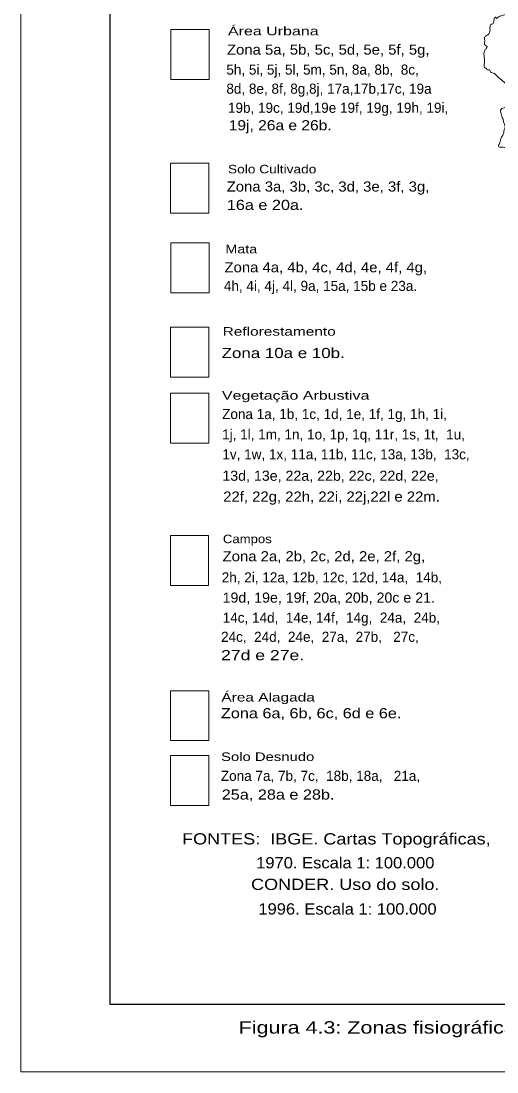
# Model space of a CAD drawing. Extents: x 854879 to 917879, y 8541948 to 8631048.
# Drawn here: x 854879 to 876061, y 8541948 to 8588670 of the extents above; entities that cross this region are included whole.
import ezdxf
from ezdxf.enums import TextEntityAlignment as Align

# ---------------------------------------------------------------- set-up
doc = ezdxf.new("R2010")
doc.units = 0
doc.header["$LTSCALE"] = 150
for name, color, linetype, lineweight in [('1', 7, 'Continuous', 13), ('18', 7, 'Continuous', 13), ('3', 7, 'Continuous', 13), ('35', 7, 'Continuous', 13), ('36', 7, 'Continuous', 13), ('44', 7, 'Continuous', 13), ('59', 7, 'Continuous', 13)]:
    doc.layers.add(name, color=color, linetype=linetype, lineweight=lineweight)
doc.layers.add('53', color=7, linetype='Continuous')
doc.layers.add('61', color=7, linetype='Continuous')

msp = doc.modelspace()

# ---------------------------------------------------------------- linework, layer by layer
at = {"layer": '1'}
msp.add_lwpolyline([(916445.6, 8586427.1), (916445.6, 8544954.2), (858846.4, 8544954.2), (858846.4, 8599885.6)], dxfattribs=at)
at = {"layer": '18'}
msp.add_spline([(877858.6, 8588369.4), (877792.5, 8588367.9), (877766.7, 8588347.9), (877740.8, 8588317.8), (877758.5, 8588312.4), (877760.4, 8588276.7), (877713.5, 8588211.2), (877611.3, 8588187.3), (877502.6, 8588217.1), (877391, 8588231.7), (877300.1, 8588268.9), (877141, 8588470.3), (877003.5, 8588600), (876874, 8588607.2), (876786, 8588659.6), (876742, 8588757.2), (876715.1, 8588818.8), (876619, 8588848.4), (876473.6, 8588960.4), (876297.4, 8588914.8), (876092.3, 8588821.3), (876038.3, 8588786.5), (875996.1, 8588843.3), (875955.1, 8588826.1), (875936.2, 8588760.1), (875927.4, 8588699.1), (875910.3, 8588594.8), (875853.5, 8588544.8), (875794.6, 8588517.7), (875760.7, 8588469.8), (875749.9, 8588296.6), (875722.2, 8588167.1), (875654.2, 8588058.5), (875579.7, 8588013.9), (875499.1, 8587918.3), (875505.3, 8587839.2), (875516.9, 8587775.2), (875502, 8587653.1), (875569.3, 8587578.1), (875616.8, 8587534), (875577.2, 8587447.9), (875509.3, 8587349.6), (875493.7, 8587044), (875499.8, 8586814.4), (875488, 8586725.4), (875498.6, 8586607.9), (875510.9, 8586582.2), (875564.3, 8586583.9), (875608.8, 8586514.4), (875659.4, 8586503.3), (875720.3, 8586497.3), (875799.8, 8586388.9), (875906, 8586356.6), (876043.7, 8586242.2), (876464.1, 8585868.2), (876558, 8585716.3), (876568.6, 8585598.8), (876552.5, 8585548.1), (876513.7, 8585510.5), (876528.1, 8585464.4), (876525, 8585433.8), (876491.8, 8585424.2), (876511.1, 8585365.2), (876474.7, 8585322.5), (876467.9, 8585225.7), (876525.5, 8585033.6), (876534.5, 8584967.2), (876500.1, 8584891.2), (876435.5, 8584836.2), (876315.4, 8584802.5), (876240.7, 8584747.6), (876213.8, 8584661.4), (876244.8, 8584548.7), (876270.8, 8584438.7), (876322.3, 8584333.3), (876355.2, 8584182.3), (876401.2, 8584054.1), (876416.7, 8583923.9), (876390.3, 8583868.2), (876362.2, 8583718.2), (876316.8, 8583599.2), (876256.6, 8583503.3), (876213.6, 8583371.4), (876191.2, 8583251.9), (876144, 8583176.2), (876122.3, 8583100.1), (876253.8, 8583057.2), (876396.1, 8583054.9), (876535.4, 8583029.7), (877188.5, 8582871.2), (877247.2, 8582888.1)], degree=3, dxfattribs=at)
at = {"layer": '3'}
msp.add_spline([(877858.6, 8588369.4), (877792.5, 8588367.9), (877766.7, 8588347.9), (877740.8, 8588317.8), (877758.5, 8588312.4), (877760.4, 8588276.7), (877713.5, 8588211.2), (877611.3, 8588187.3), (877502.6, 8588217.1), (877391, 8588231.7), (877300.1, 8588268.9), (877141, 8588470.3), (877003.5, 8588600), (876874, 8588607.2), (876786, 8588659.6), (876742, 8588757.2), (876715.1, 8588818.8), (876619, 8588848.4), (876473.6, 8588960.4), (876297.4, 8588914.8), (876092.3, 8588821.3), (876038.3, 8588786.5), (875996.1, 8588843.3), (875955.1, 8588826.1), (875936.2, 8588760.1), (875927.4, 8588699.1), (875910.3, 8588594.8), (875853.5, 8588544.8), (875794.6, 8588517.7), (875760.7, 8588469.8), (875749.9, 8588296.6), (875722.2, 8588167.1), (875654.2, 8588058.5), (875579.7, 8588013.9), (875499.1, 8587918.3), (875505.3, 8587839.2), (875516.9, 8587775.2), (875502, 8587653.1), (875569.3, 8587578.1), (875616.8, 8587534), (875577.2, 8587447.9), (875509.3, 8587349.6), (875493.7, 8587044), (875499.8, 8586814.4), (875488, 8586725.4), (875498.6, 8586607.9), (875510.9, 8586582.2), (875564.3, 8586583.9), (875608.8, 8586514.4), (875659.4, 8586503.3), (875720.3, 8586497.3), (875799.8, 8586388.9), (875906, 8586356.6), (876043.7, 8586242.2), (876464.1, 8585868.2), (876558, 8585716.3), (876568.6, 8585598.8), (876552.5, 8585548.1), (876513.7, 8585510.5), (876528.1, 8585464.4), (876525, 8585433.8), (876491.8, 8585424.2), (876511.1, 8585365.2), (876474.7, 8585322.5), (876467.9, 8585225.7), (876525.5, 8585033.6), (876534.5, 8584967.2), (876500.1, 8584891.2), (876435.5, 8584836.2), (876315.4, 8584802.5), (876240.7, 8584747.6), (876213.8, 8584661.4), (876244.8, 8584548.7), (876270.8, 8584438.7), (876322.3, 8584333.3), (876355.2, 8584182.3), (876401.2, 8584054.1), (876416.7, 8583923.9), (876390.3, 8583868.2), (876362.2, 8583718.2), (876316.8, 8583599.2), (876256.6, 8583503.3), (876213.6, 8583371.4), (876191.2, 8583251.9), (876144, 8583176.2), (876122.3, 8583100.1), (876253.8, 8583057.2), (876396.1, 8583054.9), (876535.4, 8583029.7), (877188.5, 8582871.2), (877247.2, 8582888.1)], degree=3, dxfattribs=at)
at = {"layer": '35'}
for points in [[(861545.5, 8588289.7), (863245.1, 8588289.7), (863245.1, 8586070.6), (861545.5, 8586070.6)], [(861537.2, 8582352.5), (863236.9, 8582352.5), (863236.9, 8580133.5), (861537.2, 8580133.5)], [(861551.1, 8578803.7), (863250.8, 8578803.7), (863250.8, 8576584.7), (861551.1, 8576584.7)], [(861537.2, 8575053.6), (863236.9, 8575053.6), (863236.9, 8572834.5), (861537.2, 8572834.5)], [(861537.2, 8572123.1), (863236.9, 8572123.1), (863236.9, 8569904.1), (861537.2, 8569904.1)], [(861526.8, 8565799), (863226.4, 8565799), (863226.4, 8563580), (861526.8, 8563580)], [(861537.2, 8558898.6), (863236.9, 8558898.6), (863236.9, 8556679.5), (861537.2, 8556679.5)], [(861537, 8556016.2), (863236.7, 8556016.2), (863236.7, 8553797.2), (861537, 8553797.2)]]:
    msp.add_lwpolyline(points, close=True, dxfattribs=at)
at = {"layer": '36'}
msp.add_lwpolyline([(854878.6, 8541948.4), (917878.6, 8541948.4), (917878.6, 8631048.4), (854878.6, 8631048.4)], close=True, dxfattribs=at)
at = {"layer": '36', "lineweight": 25}
msp.add_lwpolyline([(858846.4, 8628560.7), (916445.6, 8628560.7), (916445.6, 8544954.2), (858846.4, 8544954.2)], close=True, dxfattribs=at)
at = {"layer": '44'}
msp.add_lwpolyline([(858846.4, 8628560.7), (916445.6, 8628560.7), (916445.6, 8544954.2), (858846.4, 8544954.2)], close=True, dxfattribs=at)

# ---------------------------------------------------------------- texts
at = {"layer": '35', "width": 1.05}
msp.add_text('19d, 19e, 19f, 20a, 20b, 20c e 21.', height=450, dxfattribs=at).set_placement((863850, 8562812.7))
at = {"layer": '53'}
for s, width, p in [('FONTES:  IBGE. Cartas Topográficas,', 1.2, (868913.3, 8552062.6)), ('1970. Escala 1: 100.000', 1.1, (869308.9, 8550999.4)), ('CONDER. Uso do solo.', 1.2, (869308.9, 8550039.6)), ('1996. Escala 1: 100.000', 1.1, (869408.2, 8548947.5))]:
    msp.add_text(s, height=500, dxfattribs=dict(at, width=width)).set_placement(p, align=Align.CENTER)
at = {"layer": '59'}
for s, height, width, p in [('Área Urbana', 380, 1.4, (864088.8, 8588035.6)), ('Zona 5a, 5b, 5c, 5d, 5e, 5f, 5g,', 450, 1.1, (864044.4, 8587174.6)), ('19j, 26a e 26b.', 450, 1.15, (864123.8, 8583811.9)), ('Solo Cultivado', 380, 1.2, (864090.1, 8581897.2)), ('Zona 3a, 3b, 3c, 3d, 3e, 3f, 3g,', 450, 1.1, (864033.1, 8581087.7)), ('16a e 20a.', 450, 1.2, (864037.8, 8580269.9)), ('Mata', 380, 1.25, (863975.8, 8578342.4)), ('Zona 4a, 4b, 4c, 4d, 4e, 4f, 4g,', 450, 1.1, (863934.1, 8577498.6)), ('Reflorestamento', 380, 1.35, (863852.2, 8574680.9)), ('Zona 10a e 10b.', 450, 1.25, (863807.8, 8573687.1)), ('Vegetação Arbustiva', 380, 1.4, (863819.5, 8571837.6)), ('13d, 13e, 22a, 22b, 22c, 22d, 22e, ', 450, 1.05, (863839.9, 8568231)), ('22f, 22g, 22h, 22i, 22j,22l e 22m.', 450, 1.1, (863877, 8567304.3)), ('Campos', 380, 1.15, (863863, 8565457.4)), ('Zona 2a, 2b, 2c, 2d, 2e, 2f, 2g,', 450, 1.1, (863850, 8564651.8)), ('27d e 27e.', 450, 1.3, (863781.6, 8560255.3)), ('Área Alagada', 380, 1.35, (863796.8, 8558417.6)), ('Zona 6a, 6b, 6c, 6d e 6e.', 450, 1.2, (863776, 8557674)), ('Solo Desnudo', 380, 1.3, (863782, 8555773.5)), ('25a, 28a e 28b.', 450, 1.2, (863811, 8554057.8))]:
    msp.add_text(s, height=height, dxfattribs=dict(at, width=width)).set_placement(p)
for s, p in [('5h, 5i, 5j, 5l, 5m, 5n, 8a, 8b,  8c,', (864017.8, 8586285.4)), ('8d, 8e, 8f, 8g,8j, 17a,17b,17c, 19a', (864017.8, 8585437.3)), ('19b, 19c, 19d,19e 19f, 19g, 19h, 19i,', (864088.5, 8584589.3)), ('4h, 4i, 4j, 4l, 9a, 15a, 15b e 23a.', (863906.9, 8576669.4)), ('Zona 1a, 1b, 1c, 1d, 1e, 1f, 1g, 1h, 1i, ', (863829.2, 8570973.7)), ('1j, 1l, 1m, 1n, 1o, 1p, 1q, 11r, 1s, 1t,  1u, ', (863829.2, 8570068.5)), ('1v, 1w, 1x, 11a, 11b, 11c, 13a, 13b,  13c, ', (863839.9, 8569185.9)), ('2h, 2i, 12a, 12b, 12c, 12d, 14a,  14b,', (863810.7, 8563712.4)), ('14c, 14d,  14e, 14f,  14g,  24a,  24b, ', (863855.7, 8561923.3)), ('24c,  24d,  24e,  27a,  27b,   27c, ', (863781.6, 8561070.7)), ('Zona 7a, 7b, 7c,  18b, 18a,   21a,', (863773.9, 8554889))]:
    msp.add_text(s, height=450, dxfattribs=at).set_placement(p)
at = {"layer": '61', "width": 1.3}
msp.add_text('Figura 4.3: Zonas fisiográficas homogêneas para o uso do solo da bacia hidrográfica do rio Joanes de 1996.', height=550, dxfattribs=at).set_placement((887500.6, 8543654.7), align=Align.CENTER)

doc.saveas('drawing.dxf')
